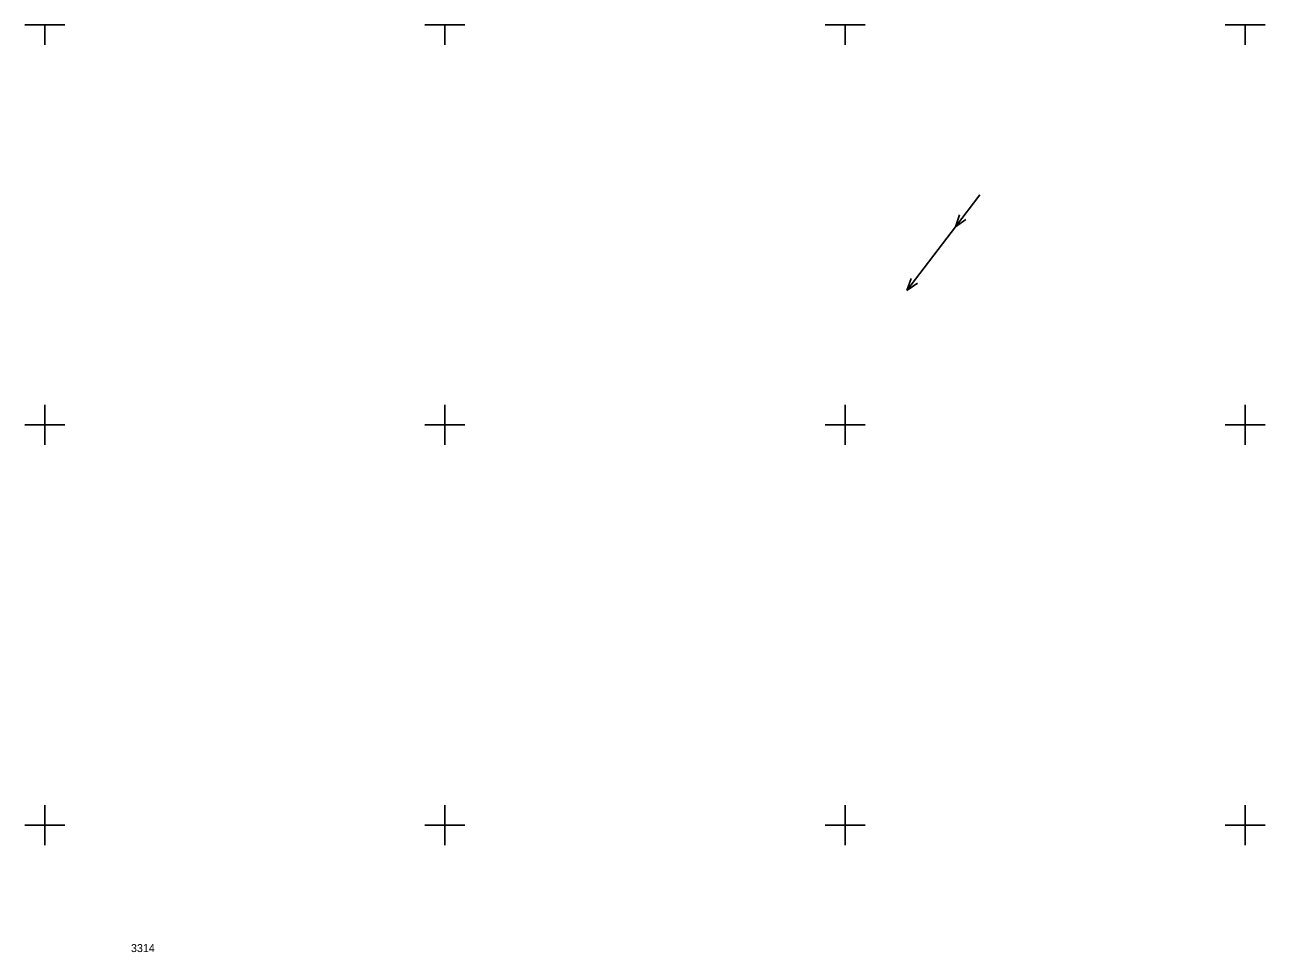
# Model space of a CAD drawing. Extents: x 6596400 to 6597200, y 5539751 to 5540251.
# Drawn here: x 6596647.5 to 6596802.5, y 5540135.1 to 5540251 of the extents above; entities that cross this region are included whole.
import ezdxf

# ---------------------------------------------------------------- set-up
doc = ezdxf.new("R2010")
doc.units = 0
for name, color, linetype in [('211-numer działki ewidencyjnej', 7, 'Continuous'), ('przewód elektroenergetyczny niskiego napięcia', 7, 'Continuous'), ('Wstawianie ramki sekcyjnej z opisem', 7, 'Continuous')]:
    doc.layers.add(name, color=color, linetype=linetype)

# ---------------------------------------------------------------- blocks, each defined once
blk = doc.blocks.new('SUEP1')
for p, q in [((0, 0), (5, 0)), ((5, 0), (3.5, 0.5)), ((5, 0), (3.5, -0.5)), ((5, 0), (15, 0)), ((15, 0), (13.5, 0.5)), ((15, 0), (13.5, -0.5))]:
    blk.add_line(p, q)
blk = doc.blocks.new('RAMKA500K')
for p, q in [((0, 248.5), (0, 251)), ((0, 251), (2.5, 251)), ((247.5, 251), (252.5, 251)), ((250, 248.5), (250, 251)), ((297.5, 251), (302.5, 251)), ((300, 248.5), (300, 251)), ((347.5, 251), (352.5, 251)), ((350, 248.5), (350, 251)), ((397.5, 251), (400, 251)), ((400, 248.5), (400, 251)), ((0, 198.5), (0, 203.5)), ((250, 198.5), (250, 203.5)), ((300, 198.5), (300, 203.5)), ((350, 198.5), (350, 203.5)), ((400, 198.5), (400, 203.5)), ((0, 201), (2.5, 201)), ((247.5, 201), (252.5, 201)), ((297.5, 201), (302.5, 201)), ((347.5, 201), (352.5, 201)), ((397.5, 201), (400, 201)), ((0, 148.5), (0, 153.5)), ((250, 148.5), (250, 153.5)), ((300, 148.5), (300, 153.5)), ((350, 148.5), (350, 153.5)), ((400, 148.5), (400, 153.5)), ((0, 151), (2.5, 151)), ((247.5, 151), (252.5, 151)), ((297.5, 151), (302.5, 151)), ((347.5, 151), (352.5, 151)), ((397.5, 151), (400, 151))]:
    blk.add_line(p, q)

msp = doc.modelspace()

# ---------------------------------------------------------------- block references
at = {"layer": 'przewód elektroenergetyczny niskiego napięcia', "rotation": -127.32700000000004}
msp.add_blockref('SUEP1', (6596766.83, 5540229.75), dxfattribs=at)
at = {"layer": 'Wstawianie ramki sekcyjnej z opisem'}
for p in [(6596400, 5540000), (6596800, 5540000)]:
    msp.add_blockref('RAMKA500K', p, dxfattribs=at)

# ---------------------------------------------------------------- texts
at = {"layer": '211-numer działki ewidencyjnej'}
msp.add_text('3314', height=1, dxfattribs=at).set_placement((6596660.77, 5540135.14))

doc.saveas('drawing.dxf')
